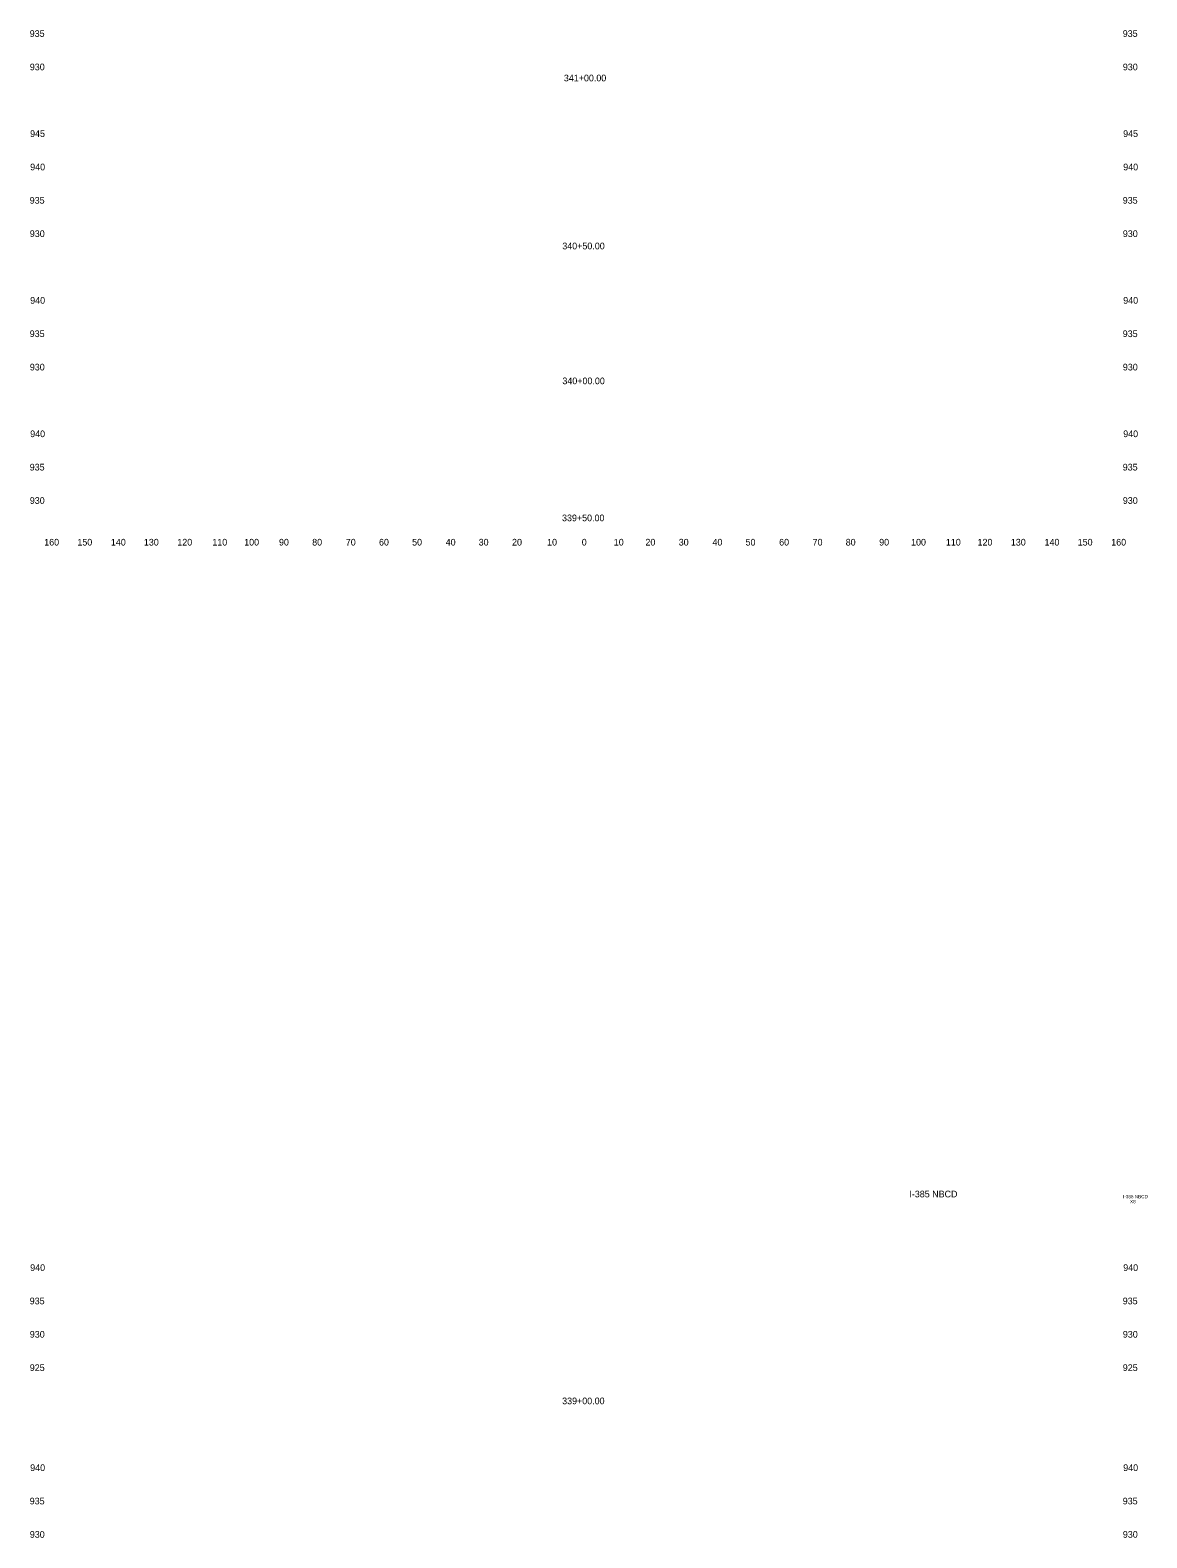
# Model space of a CAD drawing. Extents: x 4994 to 7391, y 4997 to 8804.
# Drawn here: x 4993.9 to 5328.8, y 7900 to 8352 of the extents above; entities that cross this region are included whole.
import ezdxf

# ---------------------------------------------------------------- set-up
doc = ezdxf.new("R2010")
doc.units = 0
for name, color, linetype in [('RD_SHT_ID', 7, 'Continuous'), ('RD_XS_TX_Offset', 7, 'Continuous'), ('RD_XS_TX_Station', 7, 'Continuous')]:
    doc.layers.add(name, color=color, linetype=linetype)

msp = doc.modelspace()

# ---------------------------------------------------------------- texts
at = {"layer": 'RD_SHT_ID'}
for s, height, p in [('I-385 NBCD', 2, (5257.56, 8002.06)), ('I-385 NBCD', 1, (5321.63, 8001.8)), ('X8', 1, (5323.74, 8000.3))]:
    msp.add_text(s, height=height, dxfattribs=at).set_placement(p)
at = {"layer": 'RD_XS_TX_Offset'}
for s, p in [('935', (4993.75, 8350)), ('935', (5321.55, 8350)), ('930', (4993.78, 8340)), ('930', (5321.58, 8340)), ('945', (4993.86, 8320)), ('945', (5321.66, 8320)), ('940', (4993.89, 8310)), ('940', (5321.69, 8310)), ('935', (4993.75, 8300)), ('935', (5321.55, 8300)), ('930', (4993.78, 8290)), ('930', (5321.58, 8290)), ('940', (4993.89, 8270)), ('940', (5321.69, 8270)), ('935', (4993.75, 8260)), ('935', (5321.55, 8260)), ('930', (4993.78, 8250)), ('930', (5321.58, 8250)), ('940', (4993.89, 8230)), ('940', (5321.69, 8230)), ('935', (4993.75, 8220)), ('935', (5321.55, 8220)), ('930', (4993.78, 8210)), ('930', (5321.58, 8210)), ('160', (4998.1, 8197.5)), ('150', (5008.04, 8197.5)), ('140', (5018.1, 8197.5)), ('130', (5027.99, 8197.5)), ('120', (5038.01, 8197.5)), ('110', (5048.51, 8197.5)), ('100', (5058.07, 8197.5)), ('90', (5068.5, 8197.5)), ('80', (5078.46, 8197.5)), ('70', (5088.54, 8197.5)), ('60', (5098.5, 8197.5)), ('50', (5108.43, 8197.5)), ('40', (5118.5, 8197.5)), ('30', (5128.39, 8197.5)), ('20', (5138.4, 8197.5)), ('10', (5148.91, 8197.5)), ('0', (5159.3, 8197.5)), ('0', (5159.3, 8197.5)), ('10', (5168.91, 8197.5)), ('20', (5178.4, 8197.5)), ('30', (5188.39, 8197.5)), ('40', (5198.5, 8197.5)), ('50', (5208.43, 8197.5)), ('60', (5218.5, 8197.5)), ('70', (5228.54, 8197.5)), ('80', (5238.46, 8197.5)), ('90', (5248.5, 8197.5)), ('100', (5258.07, 8197.5)), ('110', (5268.51, 8197.5)), ('120', (5278.01, 8197.5)), ('130', (5287.99, 8197.5)), ('140', (5298.1, 8197.5)), ('150', (5308.04, 8197.5)), ('160', (5318.1, 8197.5)), ('940', (4993.89, 7980)), ('940', (5321.69, 7980)), ('935', (4993.75, 7970)), ('935', (5321.55, 7970)), ('930', (4993.78, 7960)), ('930', (5321.58, 7960)), ('925', (4993.77, 7950)), ('925', (5321.57, 7950)), ('940', (4993.89, 7920)), ('940', (5321.69, 7920)), ('935', (4993.75, 7910)), ('935', (5321.55, 7910)), ('930', (4993.78, 7900)), ('930', (5321.58, 7900))]:
    msp.add_text(s, height=2, dxfattribs=at).set_placement(p)
at = {"layer": 'RD_XS_TX_Station'}
for s, p in [('341+00.00', (5153.94, 8336.68)), ('340+50.00', (5153.47, 8286.32)), ('340+00.00', (5153.5, 8245.87)), ('339+50.00', (5153.39, 8204.79)), ('339+00.00', (5153.43, 7940.03))]:
    msp.add_text(s, height=2, dxfattribs=at).set_placement(p)

doc.saveas('drawing.dxf')
